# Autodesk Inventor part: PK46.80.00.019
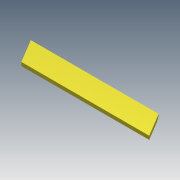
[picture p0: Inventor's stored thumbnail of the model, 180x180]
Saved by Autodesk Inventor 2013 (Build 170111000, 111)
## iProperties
Shininess: 64.0
Length Units: 11269
Angle Units: 11279
Time Units: 11290
Mass Units: 11283
Length Display Precision: 3
Angle Display Precision: 2
Compacted: True
Part Number: PK46.80.00.019
Document SubType Name: Modeling
Created: 2005-01
Material: Steel, Mild
Designer: SAlex
Manufacturer: Standard
Standards Organization: Custom
Density: 7.86 g/cm^3
Mass: 12177.1 g
Surface Area: 1953.57 cm^2
Volume: 1549.25 cm^3
Density: 0.0
Volumn: 0.0
Area: 0.0
PropertySet Name: Model Information
Control State: 0
Master: False
Checked Out: False
Checked Out Date: 2008-10-15
Last Check In Date: 2008-10-15
Author: SAlex
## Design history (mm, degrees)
derived "PK46.80.00.018.ipt"
body "Solid1"
tag "TaggingFeature4"
feature "DerivedBody::PK46.80.00.018.ipt" dims "d3" = 10
